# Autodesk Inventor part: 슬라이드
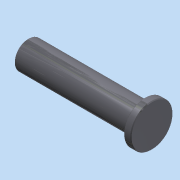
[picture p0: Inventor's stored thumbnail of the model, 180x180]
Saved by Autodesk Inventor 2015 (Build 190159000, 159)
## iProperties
Created: 2015-10
Part Number: 슬라이드
Document SubType Name: Modeling
Designer: mdu
Density: 7.86 g/cm^3
Material: 강철, 연강
Appearance: 강철 - 광택
Mass: 1603.27 g
Surface Area: 269.019 cm^2
Volume: 203.978 cm^3
Author: mdu
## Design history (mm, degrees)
sketch "스케치1"
  geometry: L1 (-75, 162)-(-75, 58) reference; L2 (-148, 110)-(22, 110); L3 (-148, 110)-(-148, 129); L4 (-148, 129)-(12, 129); L5 (12, 129)-(12, 139); L6 (12, 139)-(22, 139); L7 (22, 139)-(22, 110); 2 further points
  constraints: 12 end point, 3 parallel, 3 perpendicular, 1 midpoint, 1 point on line
  dimensions: "d0" = 58 diameter of L6 L2; "d1" = 38 diameter of L4 L2; "d2" = 10 distance of L5.end L6.end; "d3" = 170 distance of L2.start L2.end; "d4" = 73 distance between parallel lines of L3 L1
revolve "회전1" sketch "스케치1" stored, may be unused: angle "d5" = 90 deg
hole "구멍1" diameter "d11" = 13.376; stored, may be unused: countersink angle "d15" = 90 deg, drill point angle "d17" = 118 deg; dims "d9" = 10, "d10" = 10, "d12" = 22, "d13" = 4, "d14" = 2, "d16" = 25
chamfer "모따기1" distance "d6" = 1; stored, may be unused: second distance "d7" = 2, angle "d8" = 45 deg
sketch "스케치2"
  geometry: C1 r 28 at (0, 0) reference; C2 r 29 at (0, 0) reference; 1 further point
feature "경계 패치1" sketch "스케치2"
node "솔리드1"
node "참조1"
node "곡면1"
